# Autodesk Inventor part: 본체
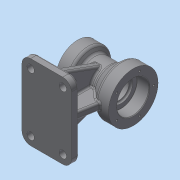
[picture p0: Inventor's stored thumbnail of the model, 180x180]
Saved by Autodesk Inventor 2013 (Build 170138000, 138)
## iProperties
Created: 2015-08
Part Number: 본체
Material: 일반
Document SubType Name: Modeling
Designer: Administrator
Density: 1 g/cm^3
Author: Administrator
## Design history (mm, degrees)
sketch "스케치1"
  geometry: L1 (0, 0)-(90, 0); L2 (0, 0)-(0, 35); L3 (0, 35)-(20, 35); L4 (20, 35)-(25.196, 26); L5 (25.196, 26)-(53.315, 26); L6 (53.315, 26)-(70, 40); L7 (70, 40)-(90, 40); L8 (90, 40)-(90, 0)
  constraints: 17 end point, 3 parallel, 2 perpendicular, 1 horizontal
  dimensions: "d0" = 90 distance of L1.start L1.end; "d2" = 70 diameter of L3 L1; "d3" = 80 diameter of L7 L1; "d4" = 60 deg angle of L5 L4; "d6" = 40 deg angle of L6 L5; "d7" = 20 distance of L6.end L7.end; "d8" = 20 distance of L2.end L3.end; "d9" = 52 diameter of L5 L1
revolve "회전1" sketch "스케치1" stored, may be unused: angle "d10" = 90 deg
node "작업 평면1"
sketch "스케치2"
  geometry: L1 (0, 61)-(80, 61); L2 (80, 61)-(80, -61); L3 (80, -61)-(0, -61); L4 (0, -61)-(0, 61); 2 further points
  constraints: 8 end point, 2 parallel, 1 coincident, 1 horizontal, 1 midpoint, 1 perpendicular, 1 vertical alignment
  dimensions: "d12" = 80 distance of L1.start L1.end; "d14" = 122 distance of L1.end L2.end
extrude "돌출1" join sketch "스케치2" distance "d15" = 12; taper "d16" = 0 deg
fillet "모깎기1" dims "d17" = 14
node "작업 평면2"
sketch "스케치6"
  geometry: L1 (-90, 61)-(-78, 61) reference; L2 (-78, 61)-(-78, -61) reference; L3 (-78, -61)-(-90, -61) reference; L4 (-90, -61)-(-90, 61) reference; L5 (-78, 51)-(-6.815, 25.091); L6 (-6.815, 25.091)-(-6.815, -25.091); L7 (-6.815, -25.091)-(-78, -51); A1 r 26 centre (0, 0) between (-6.815, 25.091) and (-6.815, -25.091) reference; 1 further point
  constraints: 6 end point, 2 point on circle, 2 point on line, 1 parallel
  dimensions: "d29" = 10 distance of L5.start L1.end; "d30" = 10 distance of L2.end L7.end; "d31" = 70 deg angle of L2 L7
extrude "돌출2" join sketch "스케치6" stored distance "d32" = 12; taper "d33" = 0 deg
sketch "스케치7"
  geometry: L1 (0, -35)-(0, 35) reference; L2 (0, 35)-(20, 35) reference; L3 (20, 35)-(25.196, 26) reference; L4 (25.196, 26)-(53.315, 26) reference; L5 (53.315, 26)-(70, 40) reference; L6 (70, 40)-(90, 40) reference; L7 (90, 40)-(90, -40) reference; L8 (90, -40)-(70, -40) reference; L9 (70, -40)-(53.315, -26) reference; L10 (53.315, -26)-(46, -26) reference; L11 (46, -26)-(46, -78) reference; L12 (46, -78)-(80, -78) reference; L13 (80, -78)-(80, -90) reference; L14 (80, -90)-(0, -90) reference; L15 (0, -90)-(0, -78) reference; L16 (0, -78)-(34, -78) reference; L17 (34, -78)-(34, -26) reference; L18 (34, -26)-(25.196, -26) reference; L19 (25.196, -26)-(20, -35) reference; L20 (20, -35)-(0, -35) reference; L21 (10, -35)-(10, -78); L22 (76.7, -40)-(70, -78); 1 further point
  constraints: 4 end point, 3 point on line, 1 midpoint, 1 perpendicular
  dimensions: "d34" = 10 distance from line of L13 L22.end; "d35" = 80 deg angle of L12 L22; "d36" = 10 distance between parallel lines of L21 L15
  node "절단 모서리 투영2"
feature "리브1" dims "d37" = 1, "d38" = 12, "d39" = 0, "d40" = 0, "d41" = 1, "d42" = 1
feature "리브2" dims "d43" = 1, "d44" = 12, "d45" = 0, "d46" = 0, "d47" = 1, "d48" = 1
sketch "스케치8"
  geometry: L1 (-30, -54)-(-30, -60); L2 (-18, -54)-(-18, -60); L3 (-47, -90)-(47, -90) reference; A1 r 26 centre (0, 0) between (-25.091, -6.815) and (-6, -25.298) reference; A2 r 6 centre (-24, -54) between (-18, -54) and (-30, -54); A3 r 6 centre (-24, -60) between (-30, -60) and (-18, -60)
  constraints: 4 end point, 4 point on circle, 4 tangent, 2 centre point, 1 vertical alignment
  dimensions: "d49" = 12 diameter of A2; "d50" = 12 diameter of A3; "d51" = 18 dimension on A3 A2; "d52" = 24 horizontal distance of A1.centre A3.centre; "d53" = 30 distance from line of L3 A3.centre
extrude "돌출3" cut sketch "스케치8" distance "d54" = 12; taper "d55" = 0 deg
sketch "스케치9"
  geometry: C1 r 6 at (14, -47); C2 r 6 at (66, -47); C3 r 6 at (66, 47); C4 r 6 at (14, 47); A1 r 14 centre (66, 47) between (80, 47) and (66, 61) reference; A2 r 14 centre (14, 47) between (14, 61) and (0, 47) reference; A3 r 14 centre (14, -47) between (0, -47) and (14, -61) reference; A4 r 14 centre (66, -47) between (66, -61) and (80, -47) reference; 1 further point
  constraints: 4 centre point, 4 coincident
  dimensions: "d56" = 12 diameter of C1; "d57" = 12 diameter of C2; "d58" = 12 diameter of C3; "d59" = 12 diameter of C4
extrude "돌출4" cut sketch "스케치9" distance "d60" = 12; taper "d61" = 0 deg
hole "구멍1" diameter "d67" = 38; stored, may be unused: countersink angle "d71" = 90 deg, drill point angle "d73" = 0 deg; dims "d65" = 10, "d66" = 10, "d68" = 6, "d69" = 52, "d70" = 20, "d72" = 23
hole "구멍2" diameter "d76" = 32; stored, may be unused: countersink angle "d80" = 90 deg, drill point angle "d82" = 0 deg; dims "d74" = 10, "d75" = 10, "d77" = 6, "d78" = 40, "d79" = 17, "d81" = 23
sketch "스케치11"
  geometry: C1 r 26 at (0, 0) reference; 1 further point
  constraints: 1 vertical alignment
  dimensions: "d83" = 33 distance of C1.centre point (0, 33)
hole "구멍3" sketch "스케치11" at (0, 33) diameter "d84" = 3.242; stored, may be unused: countersink angle "d88" = 90 deg, drill point angle "d90" = 118 deg; dims "d85" = 10, "d86" = 40, "d87" = 17, "d89" = 13
sketch "스케치12"
  geometry: C1 r 20 at (0, 0) reference; 1 further point
  constraints: 1 vertical alignment
  dimensions: "d94" = 27 distance of point (0, 27) C1.centre
hole "구멍4" sketch "스케치12" at (0, 27) diameter "d95" = 3.242; stored, may be unused: countersink angle "d99" = 90 deg, drill point angle "d101" = 118 deg; dims "d96" = 10, "d97" = 40, "d98" = 17, "d100" = 13
fillet "모깎기2" dims "d105" = 5
fillet "모깎기3" dims "d106" = 0.3
fillet "모깎기4" dims "d107" = 3
fillet "모깎기5" dims "d108" = 3
chamfer "모따기1" distance "d109" = 1; stored, may be unused: second distance "d110" = 2, angle "d111" = 45 deg
sketch "스케치14"
  geometry: L1 (-3, 37.119)-(-3, 0) reference; L2 (53, -3)-(1, -3) reference; 2 further points
  constraints: 1 other
  dimensions: "d112" = 16 distance from line of L1 point (13, 21); "d113" = 24 distance from line of point (13, 21) L2
feature "엠보싱1" sketch "스케치14" dims "d114" = 0.5, "d115" = 0
node "솔리드1"
mirror "대칭1"
pattern_circular "원형 패턴1" dims angle "d92" = 360 deg
pattern_circular "원형 패턴2" dims angle "d103" = 360 deg
node "절단 모서리 투영1"
